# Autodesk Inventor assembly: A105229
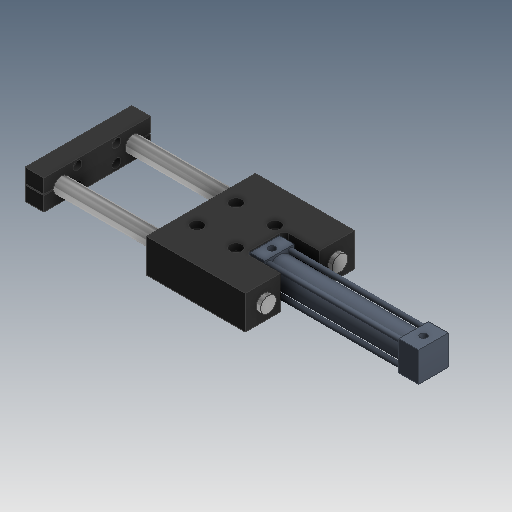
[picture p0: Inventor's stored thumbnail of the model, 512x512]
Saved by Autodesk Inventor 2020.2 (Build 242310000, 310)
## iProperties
Created: 1999-12
Part Number: A105229
Description: SLIDE,CYL,PHD,1.13BX5.00S,SDC,CUSHIONS,SHOCKPADS
Document SubType Name: Assembly
Designer: glanglot
Mass: 1096.26 g
Surface Area: 1850.33 cm^2
Volume: 1096.39 cm^3
Density: 0.999884 g/cm^3
Control State: 0
Master: False
Checked Out: False
Shininess: 0.0
Length Units: 11269
Angle Units: 11279
Time Units: 11290
Mass Units: 11283
Length Display Precision: 3
Angle Display Precision: 2
Compacted: True
Dimensions: 60x456,1x144,2 mm
Mass: 1,096 kg
DocNumber: A105229.iam
Folder: 01 - Themengebiete\Simplification\01 - Packaging machine\
VDS_Category: 3D Komponenten
Density: 0.0
Volumn: 0.0
Area: 0.0
PropertySet Name: Model Information
Author: glanglot
Revision Number: -
Title: cylinder
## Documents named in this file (6)
- D:\07 - DEMODATEN\OTX 2019 - Dataset - UPDATE - Dez2019\Designs\07-Packing machine\A105229.iam
- D:\07 - DEMODATEN\OTX 2019 - Dataset - UPDATE - Dez2019\Designs\07-Packing machine\Parts\ADSK-011815.ipt
- D:\07 - DEMODATEN\OTX 2019 - Dataset - UPDATE - Dez2019\Designs\07-Packing machine\Parts\ADSK-011818.ipt
- D:\07 - DEMODATEN\OTX 2019 - Dataset - UPDATE - Dez2019\Designs\07-Packing machine\Parts\ADSK-011817.ipt
- D:\07 - DEMODATEN\OTX 2019 - Dataset - UPDATE - Dez2019\Designs\07-Packing machine\Parts\ADSK-011819.ipt
- D:\07 - DEMODATEN\OTX 2019 - Dataset - UPDATE - Dez2019\Designs\07-Packing machine\Parts\ADSK-011816.ipt
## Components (7 placed, 5 different names)
1. ADSK-011818:1 — Mate:1, Flush:1, Flush:2, Passend:9, Passend:10
2. ADSK-011815:1 — Mate:1, Mate:2, Mate:3, Mate:6, Mate:7, Mate:8, Flush:3, Flush:4
3. ADSK-011817:1 — Mate:2, Flush:1, Mate:4, Passend:10
4. ADSK-011817:2 — Mate:3, Flush:2, Mate:5, Passend:9
5. ADSK-011819:1 — Mate:4, Mate:6
6. ADSK-011819:2 — Mate:5, Mate:7
7. ADSK-011816:1 — Mate:8, Flush:3, Flush:4
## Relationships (14: Mate 10, Flush 4)
- Mate:1: ADSK-011818:1 ↔ ADSK-011815:1
- Mate:2: ADSK-011815:1 ↔ ADSK-011817:1
- Flush:1: ADSK-011818:1 ↔ ADSK-011817:1
- Mate:3: ADSK-011815:1 ↔ ADSK-011817:2
- Flush:2: ADSK-011818:1 ↔ ADSK-011817:2
- Mate:4: ADSK-011817:1 ↔ ADSK-011819:1
- Mate:5: ADSK-011817:2 ↔ ADSK-011819:2
- Mate:6: ADSK-011815:1 ↔ ADSK-011819:1
- Mate:7: ADSK-011815:1 ↔ ADSK-011819:2
- Mate:8: ADSK-011815:1 ↔ ADSK-011816:1
- Flush:3: ADSK-011815:1 ↔ ADSK-011816:1
- Flush:4: ADSK-011815:1 ↔ ADSK-011816:1
- Passend:9 [Mate]: ADSK-011818:1 ↔ ADSK-011817:2
- Passend:10 [Mate]: ADSK-011818:1 ↔ ADSK-011817:1
